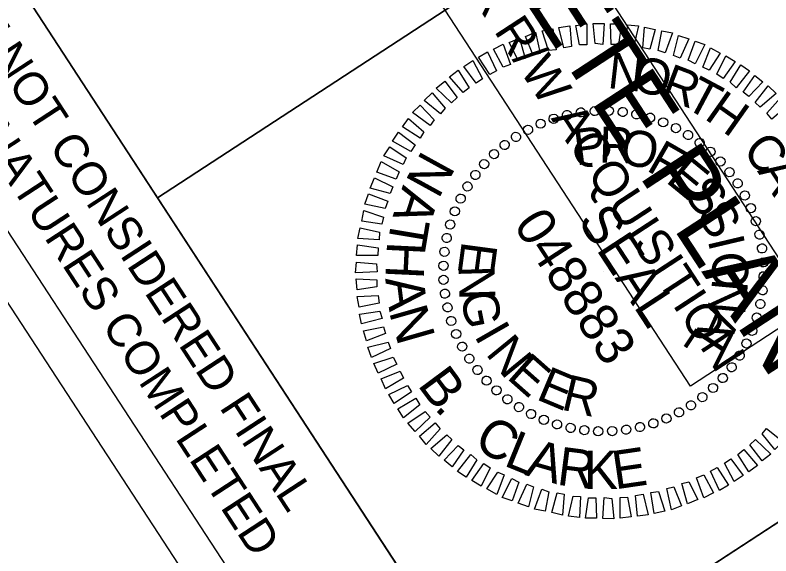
# Model space of a CAD drawing. Extents: x 1639622 to 2864602, y 842655 to 973236.
# Drawn here: x 1641227.1 to 1641350.8, y 843198.3 to 843286.8 of the extents above; entities that cross this region are included whole.
import ezdxf

# ---------------------------------------------------------------- set-up
doc = ezdxf.new("R2010")
doc.units = 0
for name, color, linetype in [('Default', 7, 'Continuous'), ('Old_Level_2', 7, 'Continuous'), ('Sheet Plan CELL', 7, 'Continuous'), ('Sheet Sticker Exception Certification CELL', 7, 'Continuous'), ('Sheet Sticker Incomplete CELL', 7, 'Continuous')]:
    doc.layers.add(name, color=color, linetype=linetype)

msp = doc.modelspace()

# ---------------------------------------------------------------- linework, layer by layer
at = {"layer": 'Default'}
msp.add_lwpolyline([(1640990.48, 843244.72), (1641153.27, 843350.95), (1641277.04, 843161.28), (1641114.25, 843055.06)], close=True, dxfattribs=at)
at = {"layer": 'Old_Level_2'}
for p, q in [((1641317.47, 843270.47), (1641317.47, 843270.47)), ((1641319.73, 843270.87), (1641319.73, 843270.87)), ((1641322.01, 843271.15), (1641322.01, 843271.15)), ((1641324.3, 843271.12), (1641324.3, 843271.12)), ((1641326.61, 843270.98), (1641326.61, 843270.98)), ((1641328.83, 843270.59), (1641328.83, 843270.59)), ((1641315.25, 843269.85), (1641315.25, 843269.85)), ((1641331.09, 843270.04), (1641331.09, 843270.04)), ((1641333.2, 843269.26), (1641333.2, 843269.26)), ((1641311.1, 843268.05), (1641311.1, 843268.05)), ((1641313.16, 843269.01), (1641313.16, 843269.01)), ((1641335.31, 843268.29), (1641335.31, 843268.29)), ((1641309.1, 843266.89), (1641309.1, 843266.89)), ((1641337.32, 843267.19), (1641337.32, 843267.19)), ((1641307.23, 843265.55), (1641307.23, 843265.55)), ((1641339.19, 843265.93), (1641339.19, 843265.93)), ((1641340.94, 843264.46), (1641340.94, 843264.46)), ((1641305.54, 843264.03), (1641305.54, 843264.03)), ((1641303.87, 843262.39), (1641303.87, 843262.39)), ((1641342.58, 843262.79), (1641342.58, 843262.79)), ((1641302.41, 843260.64), (1641302.41, 843260.64)), ((1641344.1, 843261.1), (1641344.1, 843261.1)), ((1641301.15, 843258.78), (1641301.15, 843258.78)), ((1641345.43, 843259.23), (1641345.43, 843259.23)), ((1641300.04, 843256.77), (1641300.04, 843256.77)), ((1641346.59, 843257.24), (1641346.59, 843257.24)), ((1641299.07, 843254.66), (1641299.07, 843254.66)), ((1641347.55, 843255.17), (1641347.55, 843255.17)), ((1641348.39, 843253.09), (1641348.39, 843253.09)), ((1641298.29, 843252.55), (1641298.29, 843252.55)), ((1641349.02, 843250.86), (1641349.02, 843250.86)), ((1641297.74, 843250.28), (1641297.74, 843250.28)), ((1641349.42, 843248.6), (1641349.42, 843248.6)), ((1641297.36, 843248.06), (1641297.36, 843248.06)), ((1641297.21, 843245.75), (1641297.21, 843245.75)), ((1641349.69, 843246.33), (1641349.69, 843246.33)), ((1641323.44, 843244.89), (1641323.44, 843244.89)), ((1641297.19, 843243.46), (1641297.19, 843243.46)), ((1641349.67, 843244.03), (1641349.67, 843244.03)), ((1641297.47, 843241.19), (1641297.47, 843241.19)), ((1641349.53, 843241.73), (1641349.53, 843241.73)), ((1641349.14, 843239.51), (1641349.14, 843239.51)), ((1641297.86, 843238.93), (1641297.86, 843238.93)), ((1641348.59, 843237.24), (1641348.59, 843237.24)), ((1641298.49, 843236.7), (1641298.49, 843236.7)), ((1641299.33, 843234.62), (1641299.33, 843234.62)), ((1641347.81, 843235.13), (1641347.81, 843235.13)), ((1641300.29, 843232.55), (1641300.29, 843232.55)), ((1641346.84, 843233.02), (1641346.84, 843233.02)), ((1641345.73, 843231.01), (1641345.73, 843231.01)), ((1641301.45, 843230.56), (1641301.45, 843230.56)), ((1641302.78, 843228.68), (1641302.78, 843228.68)), ((1641344.47, 843229.14), (1641344.47, 843229.14)), ((1641343.01, 843227.39), (1641343.01, 843227.39)), ((1641304.3, 843227), (1641304.3, 843227)), ((1641305.94, 843225.33), (1641305.94, 843225.33)), ((1641341.34, 843225.76), (1641341.34, 843225.76)), ((1641307.69, 843223.86), (1641307.69, 843223.86)), ((1641339.65, 843224.23), (1641339.65, 843224.23)), ((1641309.56, 843222.6), (1641309.56, 843222.6)), ((1641337.78, 843222.9), (1641337.78, 843222.9)), ((1641311.57, 843221.5), (1641311.57, 843221.5)), ((1641335.78, 843221.74), (1641335.78, 843221.74)), ((1641313.68, 843220.53), (1641313.68, 843220.53)), ((1641315.79, 843219.75), (1641315.79, 843219.75)), ((1641331.64, 843219.94), (1641331.64, 843219.94)), ((1641333.72, 843220.78), (1641333.72, 843220.78)), ((1641318.05, 843219.2), (1641318.05, 843219.2)), ((1641320.27, 843218.81), (1641320.27, 843218.81)), ((1641322.58, 843218.67), (1641322.58, 843218.67)), ((1641324.87, 843218.64), (1641324.87, 843218.64)), ((1641327.15, 843218.92), (1641327.15, 843218.92)), ((1641329.41, 843219.31), (1641329.41, 843219.31))]:
    msp.add_line(p, q, dxfattribs=at)
for points in [[(1641319.52, 843281.9), (1641318.93, 843285.1), (1641320.71, 843285.36), (1641320.69, 843281.94)], [(1641322.08, 843282.13), (1641321.74, 843285.43), (1641323.54, 843285.39), (1641323.33, 843281.96)], [(1641324.7, 843282), (1641324.58, 843285.34), (1641326.4, 843285.36), (1641325.9, 843281.99)], [(1641314.45, 843280.99), (1641313.41, 843284.21), (1641315.13, 843284.55), (1641315.68, 843281.13)], [(1641316.94, 843281.42), (1641316.12, 843284.78), (1641317.9, 843285.04), (1641318.19, 843281.63)], [(1641327.22, 843281.82), (1641327.38, 843285.21), (1641329.15, 843285.02), (1641328.41, 843281.74)], [(1641329.89, 843281.42), (1641330.17, 843284.83), (1641331.9, 843284.42), (1641331.05, 843281.19)], [(1641332.37, 843281.01), (1641332.99, 843284.21), (1641334.73, 843283.87), (1641333.54, 843280.6)], [(1641309.47, 843279.39), (1641308, 843282.31), (1641309.68, 843283), (1641310.62, 843279.66)], [(1641311.93, 843280.24), (1641310.68, 843283.3), (1641312.31, 843283.97), (1641313.08, 843280.51)], [(1641334.89, 843280.19), (1641335.71, 843283.46), (1641337.41, 843282.91), (1641336.01, 843279.75)], [(1641307.03, 843278.24), (1641305.41, 843281.19), (1641307, 843282.01), (1641308.22, 843278.73)], [(1641337.3, 843279.43), (1641338.43, 843282.53), (1641340.01, 843281.96), (1641338.47, 843278.83)], [(1641304.81, 843277.05), (1641302.99, 843279.92), (1641304.47, 843280.8), (1641305.9, 843277.67)], [(1641339.68, 843278.26), (1641340.93, 843281.44), (1641342.53, 843280.57), (1641340.75, 843277.79)], [(1641302.61, 843275.63), (1641300.58, 843278.35), (1641302.05, 843279.35), (1641303.65, 843276.33)], [(1641341.98, 843277.1), (1641343.46, 843280.13), (1641344.98, 843279.2), (1641343.01, 843276.41)], [(1641344.18, 843275.81), (1641345.92, 843278.64), (1641347.32, 843277.69), (1641345.17, 843274.9)], [(1641300.48, 843274.12), (1641298.22, 843276.69), (1641299.64, 843277.78), (1641301.46, 843274.91)], [(1641346.31, 843274.16), (1641348.23, 843276.91), (1641349.53, 843275.84), (1641347.22, 843273.46)], [(1641298.58, 843272.45), (1641296.06, 843274.85), (1641297.45, 843275.98), (1641299.5, 843273.32)], [(1641348.28, 843272.46), (1641350.39, 843275.22), (1641351.69, 843273.95), (1641349.11, 843271.7)], [(1641296.76, 843270.65), (1641294.09, 843272.82), (1641295.39, 843274.08), (1641297.5, 843271.53)], [(1641350.16, 843270.71), (1641352.46, 843273.28), (1641353.56, 843271.94), (1641350.99, 843269.76)], [(1641295.04, 843268.72), (1641292.16, 843270.82), (1641293.42, 843272.05), (1641295.74, 843269.64)], [(1641293.43, 843266.62), (1641290.51, 843268.5), (1641291.53, 843269.88), (1641294.04, 843267.67)], [(1641291.92, 843264.46), (1641288.89, 843266.14), (1641289.9, 843267.64), (1641292.58, 843265.54)], [(1641290.65, 843262.34), (1641287.49, 843263.73), (1641288.45, 843265.21), (1641291.12, 843263.41)], [(1641289.51, 843259.92), (1641286.31, 843261.1), (1641287.05, 843262.8), (1641289.96, 843261.11)], [(1641288.49, 843257.59), (1641285.24, 843258.48), (1641285.94, 843260.15), (1641288.96, 843258.67)], [(1641287.69, 843255.15), (1641284.39, 843255.82), (1641284.94, 843257.52), (1641288.14, 843256.34)], [(1641287.15, 843252.58), (1641283.86, 843253.06), (1641284.19, 843254.8), (1641287.41, 843253.7)], [(1641286.7, 843249.99), (1641283.24, 843250.24), (1641283.58, 843251.99), (1641286.79, 843251.26)], [(1641286.47, 843247.44), (1641283, 843247.43), (1641283.19, 843249.2), (1641286.52, 843248.67)], [(1641286.37, 843244.79), (1641282.84, 843244.6), (1641282.98, 843246.34), (1641286.25, 843246.09)], [(1641286.35, 843242.31), (1641283.09, 843241.8), (1641282.94, 843243.6), (1641286.31, 843243.48)], [(1641286.7, 843239.64), (1641283.41, 843238.99), (1641283.11, 843240.74), (1641286.53, 843240.91)], [(1641287.2, 843237.13), (1641283.8, 843236.28), (1641283.5, 843237.85), (1641286.83, 843238.33)], [(1641287.74, 843234.66), (1641284.62, 843233.49), (1641284.14, 843235.12), (1641287.43, 843235.77)], [(1641288.59, 843232.2), (1641285.48, 843230.73), (1641284.83, 843232.43), (1641288.19, 843233.25)], [(1641289.61, 843229.67), (1641286.57, 843228.18), (1641285.82, 843229.76), (1641289.03, 843230.8)], [(1641290.67, 843227.36), (1641287.74, 843225.62), (1641287.03, 843227.23), (1641290.14, 843228.51)], [(1641292, 843225.1), (1641289.19, 843223.2), (1641288.27, 843224.66), (1641291.34, 843226.17)], [(1641293.37, 843223), (1641290.7, 843220.87), (1641289.78, 843222.33), (1641292.71, 843224.07)], [(1641295.05, 843220.98), (1641292.6, 843218.63), (1641291.43, 843219.98), (1641294.22, 843221.93)], [(1641296.72, 843219.08), (1641294.42, 843216.51), (1641293.32, 843217.85), (1641295.89, 843220.03)], [(1641350.12, 843219.14), (1641352.79, 843216.97), (1641351.49, 843215.71), (1641349.39, 843218.26)], [(1641298.6, 843217.32), (1641296.49, 843214.57), (1641295.19, 843215.83), (1641297.77, 843218.09)], [(1641348.3, 843217.34), (1641350.82, 843214.94), (1641349.43, 843213.81), (1641347.38, 843216.46)], [(1641300.57, 843215.63), (1641298.65, 843212.87), (1641297.35, 843213.95), (1641299.66, 843216.33)], [(1641302.7, 843213.98), (1641300.96, 843211.15), (1641299.56, 843212.1), (1641301.71, 843214.88)], [(1641346.4, 843215.67), (1641348.66, 843213.09), (1641347.24, 843212.01), (1641345.42, 843214.88)], [(1641344.27, 843214.16), (1641346.3, 843211.44), (1641344.83, 843210.44), (1641343.23, 843213.46)], [(1641304.9, 843212.69), (1641303.42, 843209.66), (1641301.9, 843210.59), (1641303.87, 843213.38)], [(1641342.07, 843212.74), (1641343.89, 843209.87), (1641342.41, 843208.98), (1641340.98, 843212.12)], [(1641307.2, 843211.53), (1641305.95, 843208.34), (1641304.35, 843209.22), (1641306.13, 843212)], [(1641339.85, 843211.55), (1641341.47, 843208.6), (1641339.88, 843207.78), (1641338.66, 843211.06)], [(1641309.58, 843210.36), (1641308.46, 843207.26), (1641306.87, 843207.83), (1641308.41, 843210.96)], [(1641311.99, 843209.59), (1641311.17, 843206.32), (1641309.47, 843206.88), (1641310.87, 843210.03)], [(1641337.41, 843210.4), (1641338.88, 843207.48), (1641337.2, 843206.78), (1641336.26, 843210.13)], [(1641314.51, 843208.77), (1641313.89, 843205.58), (1641312.15, 843205.91), (1641313.34, 843209.18)], [(1641316.99, 843208.37), (1641316.71, 843204.96), (1641314.98, 843205.37), (1641315.83, 843208.59)], [(1641332.43, 843208.79), (1641333.47, 843205.58), (1641331.75, 843205.23), (1641331.2, 843208.65)], [(1641334.95, 843209.55), (1641336.2, 843206.49), (1641334.57, 843205.82), (1641333.81, 843209.28)], [(1641319.66, 843207.97), (1641319.5, 843204.57), (1641317.73, 843204.76), (1641318.47, 843208.05)], [(1641322.19, 843207.79), (1641322.3, 843204.45), (1641320.49, 843204.42), (1641320.98, 843207.79)], [(1641324.8, 843207.66), (1641325.14, 843204.36), (1641323.34, 843204.4), (1641323.55, 843207.83)], [(1641327.36, 843207.88), (1641327.95, 843204.68), (1641326.17, 843204.42), (1641326.19, 843207.85)], [(1641329.94, 843208.37), (1641330.76, 843205.01), (1641328.98, 843204.75), (1641328.69, 843208.15)]]:
    msp.add_lwpolyline(points, close=True, dxfattribs=at)
for centre, major_axis in [((1641319.73, 843270.86), (-0.106, 0.745)), ((1641322.01, 843271.08), (-0.041, 0.752)), ((1641324.3, 843271.11), (0.025, 0.753)), ((1641326.58, 843270.93), (0.09, 0.748)), ((1641315.28, 843269.82), (-0.234, 0.716)), ((1641317.48, 843270.44), (-0.171, 0.733)), ((1641328.84, 843270.56), (0.155, 0.737)), ((1641331.05, 843269.99), (0.219, 0.721)), ((1641313.14, 843269.01), (-0.296, 0.692)), ((1641333.21, 843269.23), (0.281, 0.699)), ((1641335.3, 843268.29), (0.34, 0.672)), ((1641311.08, 843268.02), (-0.355, 0.664)), ((1641337.29, 843267.17), (0.398, 0.639)), ((1641309.11, 843266.86), (-0.411, 0.631)), ((1641339.18, 843265.87), (0.452, 0.602)), ((1641307.25, 843265.53), (-0.465, 0.592)), ((1641305.51, 843264.04), (-0.515, 0.55)), ((1641340.95, 843264.42), (0.503, 0.561)), ((1641303.91, 843262.4), (-0.561, 0.503)), ((1641342.58, 843262.82), (0.55, 0.515)), ((1641344.07, 843261.09), (0.592, 0.465)), ((1641302.46, 843260.63), (-0.602, 0.452)), ((1641301.17, 843258.74), (-0.639, 0.398)), ((1641345.41, 843259.23), (0.631, 0.411)), ((1641346.57, 843257.26), (0.664, 0.355)), ((1641300.05, 843256.75), (-0.672, 0.34)), ((1641347.56, 843255.19), (0.692, 0.296)), ((1641299.1, 843254.66), (-0.699, 0.281)), ((1641298.34, 843252.51), (-0.721, 0.219)), ((1641348.37, 843253.05), (0.716, 0.234)), ((1641297.77, 843250.29), (-0.737, 0.155)), ((1641348.98, 843250.85), (0.733, 0.171)), ((1641349.4, 843248.6), (0.745, 0.106)), ((1641297.4, 843248.03), (-0.748, 0.09)), ((1641349.63, 843246.32), (0.752, 0.041)), ((1641297.23, 843245.75), (-0.753, 0.025)), ((1641349.65, 843244.04), (0.753, -0.025)), ((1641297.25, 843243.46), (-0.752, -0.041)), ((1641297.48, 843241.19), (-0.745, -0.106)), ((1641349.48, 843241.75), (0.748, -0.09)), ((1641297.9, 843238.94), (-0.733, -0.171)), ((1641349.11, 843239.5), (0.737, -0.155)), ((1641298.51, 843236.73), (-0.716, -0.234)), ((1641348.54, 843237.28), (0.721, -0.219)), ((1641347.78, 843235.12), (0.699, -0.281)), ((1641299.32, 843234.59), (-0.692, -0.296)), ((1641300.31, 843232.53), (-0.664, -0.355)), ((1641346.84, 843233.04), (0.672, -0.34)), ((1641301.48, 843230.56), (-0.631, -0.411)), ((1641345.71, 843231.04), (0.639, -0.398)), ((1641302.81, 843228.7), (-0.592, -0.465)), ((1641344.42, 843229.15), (0.602, -0.452)), ((1641304.3, 843226.96), (-0.55, -0.515)), ((1641342.97, 843227.39), (0.561, -0.503)), ((1641305.93, 843225.36), (-0.503, -0.561)), ((1641341.37, 843225.75), (0.515, -0.55)), ((1641307.7, 843223.91), (-0.452, -0.602)), ((1641339.63, 843224.26), (0.465, -0.592)), ((1641309.59, 843222.62), (-0.398, -0.639)), ((1641337.77, 843222.93), (0.411, -0.631)), ((1641311.58, 843221.5), (-0.34, -0.672)), ((1641335.8, 843221.76), (0.355, -0.664)), ((1641313.67, 843220.55), (-0.281, -0.699)), ((1641333.74, 843220.77), (0.296, -0.692)), ((1641315.83, 843219.79), (-0.219, -0.721)), ((1641318.04, 843219.23), (-0.155, -0.737)), ((1641320.3, 843218.85), (-0.09, -0.748)), ((1641327.15, 843218.93), (0.106, -0.745)), ((1641329.4, 843219.35), (0.171, -0.733)), ((1641331.6, 843219.97), (0.234, -0.716)), ((1641322.58, 843218.68), (-0.025, -0.753)), ((1641324.87, 843218.7), (0.041, -0.752))]:
    msp.add_ellipse(centre, major_axis=major_axis, ratio=0.999708, dxfattribs=at)
at = {"layer": 'Sheet Plan CELL'}
msp.add_line((1641344.62, 843318.36), (1641250.45, 843256.89), dxfattribs=at)
for points in [[(1641430.74, 843255.12), (1640611, 844511.36), (1639731.66, 843937.55), (1640551.38, 842681.33)], [(1639731.66, 843937.55), (1640610.97, 844511.36), (1641321.42, 843422.68), (1641195.75, 843340.66), (1641305.06, 843173.13), (1640551.38, 842681.33)], [(1641289.95, 843402.15), (1641344.62, 843318.36), (1641250.4, 843256.87), (1641195.75, 843340.66)], [(1641344.62, 843318.36), (1641399.27, 843234.63), (1641305.06, 843173.13), (1641250.4, 843256.87)]]:
    msp.add_lwpolyline(points, close=True, dxfattribs=at)
at = {"layer": 'Sheet Sticker Exception Certification CELL'}
for p, q in [((1641195.75, 843340.66), (1641305.07, 843173.14)), ((1641195.75, 843340.66), (1641305.07, 843173.14)), ((1641285.39, 843160.3), (1641176.07, 843327.82)), ((1641285.39, 843160.3), (1641176.07, 843327.82))]:
    msp.add_line(p, q, dxfattribs=at)
at = {"layer": 'Sheet Sticker Incomplete CELL'}
msp.add_lwpolyline([(1641257.35, 843349.17), (1641277.03, 843362.02), (1641357.36, 843238.91), (1641337.68, 843226.06)], close=True, dxfattribs=at)

# ---------------------------------------------------------------- texts
at = {"layer": 'Default'}
for s, rotation, p in [('N', 241.2032, (1641293.81, 843264.87)), ('A', 251.815, (1641290.63, 843259.08)), ('T', 260.5613, (1641288.85, 843253.93)), ('H', 267.2892, (1641288.02, 843249.82)), ('A', 277.167, (1641287.69, 843243.67)), ('N', 285.9133, (1641288.28, 843238.25)), ('B', 306.617, (1641292.88, 843226.25)), ('.', 314.2318, (1641295.61, 843222.37)), ('C', 328.3146, (1641301.92, 843216.28)), ('L', 337.7948, (1641306.92, 843213.13)), ('A', 344.0029, (1641310.44, 843211.53)), ('R', 352.7492, (1641315.66, 843209.94)), ('E', 8.3457, (1641325.33, 843209.14)), ('K', 0.1499, (1641320.22, 843209.23))]:
    msp.add_text(s, height=6.27, rotation=rotation, dxfattribs=at).set_placement(p)
at = {"layer": 'Old_Level_2'}
for s, height, rotation, p in [('N', 5.9, 353.5494, (1641323.97, 843274.87)), ('O', 5.9, 346.3476, (1641327.83, 843274.58)), ('R', 5.9, 339.1464, (1641332.53, 843273.42)), ('T', 5.9, 331.9457, (1641336.43, 843271.76)), ('H', 5.9, 324.7454, (1641339.77, 843269.92)), ('P', 5.9, 7.5248, (1641318.93, 843262.17)), ('R', 5.9, 358.1656, (1641322.64, 843262.67)), ('O', 5.9, 348.8071, (1641325.79, 843262.59)), ('C', 5.9, 310.3458, (1641345.96, 843264.51)), ('F', 5.9, 330.0929, (1641330.28, 843261.46)), ('E', 5.9, 320.737, (1641333.45, 843259.57)), ('A', 5.9, 303.1462, (1641348.54, 843261.27)), ('S', 5.9, 311.3815, (1641336.38, 843257.2)), ('SEAL', 6.273, 303.1259, (1641319.11, 843253.14)), ('S', 5.9, 302.0263, (1641338.54, 843254.12)), ('048883', 6.275, 303.1259, (1641308.58, 843252.45)), ('I', 5.9, 283.3155, (1641340.46, 843249.98)), ('E', 5.9, 262.4028, (1641300.27, 843249.91)), ('O', 5.9, 273.9594, (1641341.02, 843247.84)), ('N', 5.9, 271.7599, (1641299.69, 843245.73)), ('N', 5.9, 264.6025, (1641341.26, 843243.77)), ('G', 5.9, 281.1161, (1641299.97, 843241.12)), ('A', 5.9, 245.8862, (1641340.68, 843239.77)), ('I', 5.9, 299.8271, (1641302.17, 843234.33)), ('N', 5.9, 309.1823, (1641304.01, 843231.34)), ('L', 5.9, 236.5268, (1641338.84, 843236.06)), ('E', 5.9, 318.5377, (1641307.43, 843227.41)), ('E', 5.9, 337.25, (1641312.23, 843223.97)), ('R', 5.9, 346.6073, (1641316.35, 843222.27))]:
    msp.add_text(s, height=height, rotation=rotation, dxfattribs=at).set_placement(p)
at = {"layer": 'Sheet Sticker Exception Certification CELL'}
for s, p in [('DOCUMENT NOT CONSIDERED FINAL', (1641198.6, 843317.37)), ('DOCUMENT NOT CONSIDERED FINAL', (1641198.6, 843317.37)), ('UNLESS ALL SIGNATURES COMPLETED', (1641188.46, 843316.8)), ('UNLESS ALL SIGNATURES COMPLETED', (1641188.46, 843316.8))]:
    msp.add_text(s, height=5.5, rotation=303.1259, dxfattribs=at).set_placement(p)
at = {"layer": 'Sheet Sticker Incomplete CELL'}
for s, height, p in [('INCOMPLETE PLANS', 11.52, (1641272.04, 843348.07)), ('DO NOT USE FOR R/W ACQUISITION', 5.76, (1641267.99, 843341.55))]:
    msp.add_text(s, height=height, rotation=303.1259, dxfattribs=at).set_placement(p)

doc.saveas('drawing.dxf')
